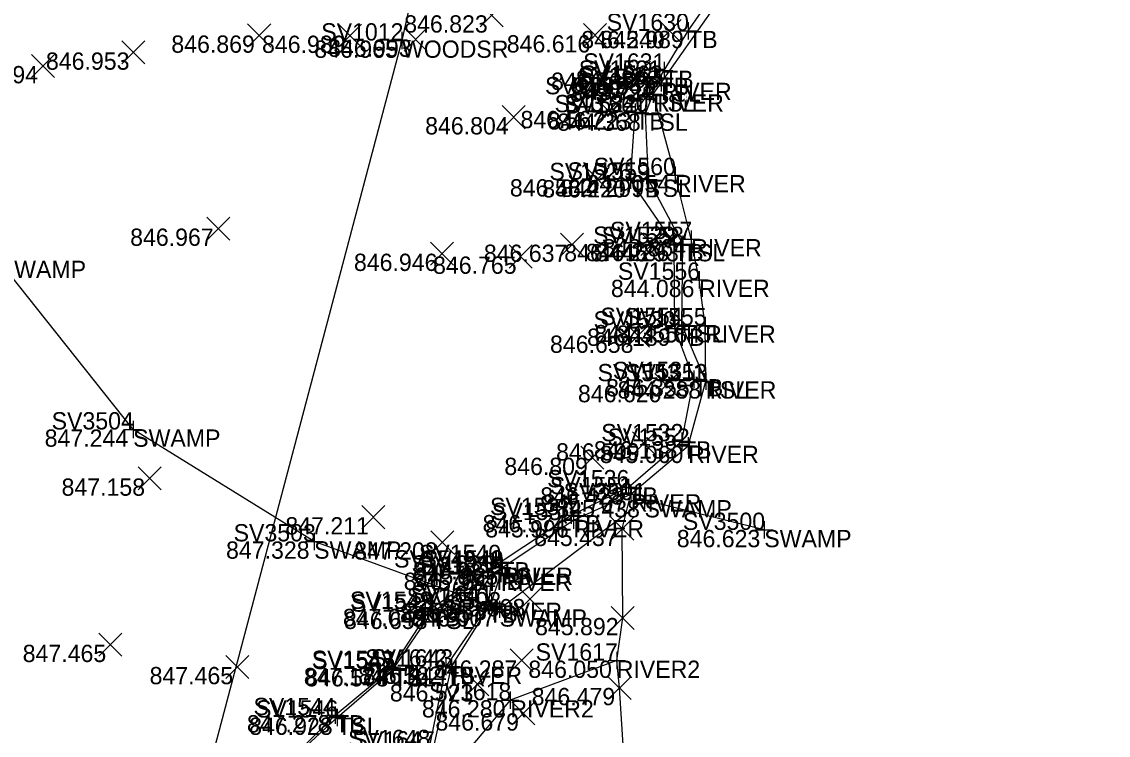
# Model space of a CAD drawing. Extents: x 2228183 to 2230895, y 679226 to 682223.
# Drawn here: x 2228345.6 to 2228408.5, y 680526.8 to 680568.1 of the extents above; entities that cross this region are included whole.
import ezdxf

# ---------------------------------------------------------------- set-up
doc = ezdxf.new("R2010")
doc.units = 0
for name, color, linetype in [('HY_X_Water_Edge', 7, 'Continuous'), ('SC_Scratch1', 7, 'Continuous'), ('SV_P_Control_Cells_Set', 7, 'Continuous'), ('SV_X_Random_Point', 7, 'Continuous'), ('SV_X_Shot_Marker', 7, 'Continuous'), ('SV_X_Terrain_Boundary', 7, 'Continuous'), ('SV_X_Text_Comment', 7, 'Continuous'), ('SV_X_Toe_of_Slope', 7, 'Continuous'), ('SV_X_Top_of_Bank', 7, 'Continuous'), ('VG_X_Tree_Line_Rt', 7, 'Continuous')]:
    doc.layers.add(name, color=color, linetype=linetype)

msp = doc.modelspace()

# ---------------------------------------------------------------- linework, layer by layer
at = {"layer": 'HY_X_Water_Edge'}
for points in [[(2228351.874, 680498.059), (2228352.446, 680499.738), (2228356.332, 680506.475), (2228359.575, 680512.281), (2228364.446, 680519.192), (2228367.217, 680520.658), (2228368.827, 680522.654), (2228367.913, 680524.402), (2228369.445, 680526.065), (2228370.483, 680530.802), (2228372.796, 680534.496), (2228373.339, 680536.179), (2228373.425, 680536.53), (2228377.537, 680539.273), (2228380.858, 680540.77), (2228384.182, 680543.574), (2228385.199, 680547.303), (2228385.16, 680550.533), (2228384.814, 680553.173), (2228384.351, 680555.526), (2228383.424, 680559.226), (2228382.159, 680563.898), (2228382.611, 680564.564)], [(2228388.587, 680538.705), (2228381.654, 680540.428), (2228373.267, 680534.114), (2228362.534, 680538.041), (2228352.058, 680544.515), (2228344.28, 680554.272), (2228336.684, 680545.185), (2228336.291, 680530.248), (2228335.4, 680519.473), (2228335.533, 680511.573), (2228332.556, 680502.567), (2228338.972, 680492.245), (2228338.927, 680481.209), (2228345.953, 680472.044), (2228352.301, 680471.046)], [(2228380.046, 680531.148), (2228373.886, 680528.859), (2228371.308, 680525.808), (2228369.351, 680519.348), (2228367.828, 680517.799), (2228365.066, 680517.912), (2228360.832, 680511.915), (2228358.717, 680505.916)]]:
    msp.add_lwpolyline(points, dxfattribs=at)
at = {"layer": 'SV_X_Random_Point'}
for p, q in [((2228372.144, 680567.799), (2228373.478, 680569.134)), ((2228372.144, 680569.134), (2228373.478, 680567.799)), ((2228358.685, 680566.633), (2228360.019, 680567.968)), ((2228358.685, 680567.968), (2228360.019, 680566.633)), ((2228363.933, 680566.623), (2228365.267, 680567.958)), ((2228363.933, 680567.958), (2228365.267, 680566.623)), ((2228367.739, 680566.399), (2228369.073, 680567.734)), ((2228367.739, 680567.734), (2228369.073, 680566.399)), ((2228378.119, 680566.649), (2228379.453, 680567.984)), ((2228378.119, 680567.984), (2228379.453, 680566.649)), ((2228382.441, 680566.89), (2228383.775, 680568.225)), ((2228382.441, 680568.225), (2228383.775, 680566.89)), ((2228351.407, 680565.652), (2228352.741, 680566.987)), ((2228351.407, 680566.987), (2228352.741, 680565.652)), ((2228346.173, 680564.867), (2228347.507, 680566.202)), ((2228346.173, 680566.202), (2228347.507, 680564.867)), ((2228380.664, 680564.486), (2228381.998, 680565.821)), ((2228380.664, 680565.821), (2228381.998, 680564.486)), ((2228373.412, 680561.91), (2228374.746, 680563.245)), ((2228373.412, 680563.245), (2228374.746, 680561.91)), ((2228378.905, 680562.27), (2228380.239, 680563.605)), ((2228378.905, 680563.605), (2228380.239, 680562.27)), ((2228378.268, 680558.322), (2228379.602, 680559.657)), ((2228378.268, 680559.657), (2228379.602, 680558.322)), ((2228356.312, 680555.466), (2228357.646, 680556.801)), ((2228356.312, 680556.801), (2228357.646, 680555.466)), ((2228376.785, 680554.537), (2228378.119, 680555.872)), ((2228376.785, 680555.872), (2228378.119, 680554.537)), ((2228381.443, 680554.569), (2228382.777, 680555.904)), ((2228381.443, 680555.904), (2228382.777, 680554.569)), ((2228369.273, 680554.014), (2228370.607, 680555.349)), ((2228369.273, 680555.349), (2228370.607, 680554.014)), ((2228373.819, 680553.85), (2228375.153, 680555.185)), ((2228373.819, 680555.185), (2228375.153, 680553.85)), ((2228380.617, 680549.279), (2228381.951, 680550.614)), ((2228380.617, 680550.614), (2228381.951, 680549.279)), ((2228382.249, 680546.42), (2228383.583, 680547.755)), ((2228382.249, 680547.755), (2228383.583, 680546.42)), ((2228380.954, 680543.049), (2228382.288, 680544.384)), ((2228380.954, 680544.384), (2228382.288, 680543.049)), ((2228377.96, 680542.215), (2228379.294, 680543.55)), ((2228377.96, 680543.55), (2228379.294, 680542.215)), ((2228352.345, 680541.016), (2228353.679, 680542.351)), ((2228352.345, 680542.351), (2228353.679, 680541.016)), ((2228365.284, 680538.776), (2228366.618, 680540.111)), ((2228365.284, 680540.111), (2228366.618, 680538.776)), ((2228379.696, 680538.107), (2228381.03, 680539.442)), ((2228379.696, 680539.442), (2228381.03, 680538.107)), ((2228369.283, 680537.322), (2228370.617, 680538.657)), ((2228369.283, 680538.657), (2228370.617, 680537.322)), ((2228374.355, 680534.043), (2228375.689, 680535.378)), ((2228374.355, 680535.378), (2228375.689, 680534.043)), ((2228379.726, 680532.948), (2228381.06, 680534.283)), ((2228379.726, 680534.283), (2228381.06, 680532.948)), ((2228350.067, 680531.398), (2228351.401, 680532.733)), ((2228350.067, 680532.733), (2228351.401, 680531.398)), ((2228373.883, 680530.494), (2228375.217, 680531.829)), ((2228373.883, 680531.829), (2228375.217, 680530.494)), ((2228357.412, 680530.114), (2228358.746, 680531.449)), ((2228357.412, 680531.449), (2228358.746, 680530.114)), ((2228371.313, 680529.118), (2228372.647, 680530.453)), ((2228371.313, 680530.453), (2228372.647, 680529.118)), ((2228379.541, 680528.902), (2228380.875, 680530.237)), ((2228379.541, 680530.237), (2228380.875, 680528.902)), ((2228373.971, 680527.434), (2228375.305, 680528.769)), ((2228373.971, 680528.769), (2228375.305, 680527.434))]:
    msp.add_line(p, q, dxfattribs=at)
at = {"layer": 'SV_X_Shot_Marker'}
for p, q in [((2228384.177, 680568.068), (2228384.177, 680567.068)), ((2228367.114, 680567.008), (2228368.114, 680567.008)), ((2228367.614, 680567.508), (2228367.614, 680566.508)), ((2228367.614, 680567.008), (2228367.614, 680567.008)), ((2228383.677, 680567.568), (2228384.677, 680567.568)), ((2228384.177, 680567.568), (2228384.177, 680567.568)), ((2228382.784, 680565.766), (2228382.784, 680564.766)), ((2228382.284, 680565.266), (2228383.284, 680565.266)), ((2228382.529, 680565.357), (2228382.529, 680564.357)), ((2228382.784, 680565.266), (2228382.784, 680565.266)), ((2228382.029, 680564.857), (2228383.029, 680564.857)), ((2228382.111, 680564.564), (2228383.111, 680564.564)), ((2228382.529, 680564.857), (2228382.529, 680564.857)), ((2228382.611, 680565.064), (2228382.611, 680564.064)), ((2228382.611, 680564.564), (2228382.611, 680564.564)), ((2228381.659, 680563.898), (2228382.659, 680563.898)), ((2228381.659, 680563.898), (2228382.659, 680563.898)), ((2228382.159, 680564.398), (2228382.159, 680563.398)), ((2228382.159, 680564.398), (2228382.159, 680563.398)), ((2228382.159, 680563.898), (2228382.159, 680563.898)), ((2228382.159, 680563.898), (2228382.159, 680563.898)), ((2228381.121, 680563.36), (2228381.121, 680562.36)), ((2228381.702, 680563.288), (2228381.702, 680562.288)), ((2228380.621, 680562.86), (2228381.621, 680562.86)), ((2228381.121, 680562.86), (2228381.121, 680562.86)), ((2228381.202, 680562.788), (2228382.202, 680562.788)), ((2228381.702, 680562.788), (2228381.702, 680562.788)), ((2228380.853, 680559.434), (2228380.853, 680558.434)), ((2228381.881, 680559.464), (2228381.881, 680558.464)), ((2228383.424, 680559.726), (2228383.424, 680558.726)), ((2228380.353, 680558.934), (2228381.353, 680558.934)), ((2228380.853, 680558.934), (2228380.853, 680558.934)), ((2228381.381, 680558.964), (2228382.381, 680558.964)), ((2228381.881, 680558.964), (2228381.881, 680558.964)), ((2228382.924, 680559.226), (2228383.924, 680559.226)), ((2228383.424, 680559.226), (2228383.424, 680559.226)), ((2228383.363, 680555.752), (2228383.363, 680554.752)), ((2228383.873, 680555.738), (2228383.873, 680554.738)), ((2228384.351, 680556.026), (2228384.351, 680555.026)), ((2228382.863, 680555.252), (2228383.863, 680555.252)), ((2228383.363, 680555.252), (2228383.363, 680555.252)), ((2228383.373, 680555.238), (2228384.373, 680555.238)), ((2228383.851, 680555.526), (2228384.851, 680555.526)), ((2228383.873, 680555.238), (2228383.873, 680555.238)), ((2228384.351, 680555.526), (2228384.351, 680555.526)), ((2228384.314, 680553.173), (2228385.314, 680553.173)), ((2228384.814, 680553.673), (2228384.814, 680552.673)), ((2228384.814, 680553.173), (2228384.814, 680553.173)), ((2228383.414, 680550.851), (2228383.414, 680549.851)), ((2228383.823, 680551.058), (2228383.823, 680550.058)), ((2228385.16, 680551.033), (2228385.16, 680550.033)), ((2228382.914, 680550.351), (2228383.914, 680550.351)), ((2228383.323, 680550.558), (2228384.323, 680550.558)), ((2228383.414, 680550.351), (2228383.414, 680550.351)), ((2228383.823, 680550.558), (2228383.823, 680550.558)), ((2228384.66, 680550.533), (2228385.66, 680550.533)), ((2228385.16, 680550.533), (2228385.16, 680550.533)), ((2228384.501, 680547.928), (2228384.501, 680546.928)), ((2228385.199, 680547.803), (2228385.199, 680546.803)), ((2228385.199, 680547.803), (2228385.199, 680546.803)), ((2228384.001, 680547.428), (2228385.001, 680547.428)), ((2228384.501, 680547.428), (2228384.501, 680547.428)), ((2228384.699, 680547.303), (2228385.699, 680547.303)), ((2228384.699, 680547.303), (2228385.699, 680547.303)), ((2228385.199, 680547.303), (2228385.199, 680547.303)), ((2228385.199, 680547.303), (2228385.199, 680547.303)), ((2228352.058, 680545.015), (2228352.058, 680544.015)), ((2228351.558, 680544.515), (2228352.558, 680544.515)), ((2228352.058, 680544.515), (2228352.058, 680544.515)), ((2228383.322, 680543.833), (2228384.322, 680543.833)), ((2228383.822, 680544.333), (2228383.822, 680543.333)), ((2228383.822, 680543.833), (2228383.822, 680543.833)), ((2228384.182, 680544.074), (2228384.182, 680543.074)), ((2228383.682, 680543.574), (2228384.682, 680543.574)), ((2228384.182, 680543.574), (2228384.182, 680543.574)), ((2228380.722, 680541.67), (2228380.722, 680540.67)), ((2228380.858, 680541.27), (2228380.858, 680540.27)), ((2228380.222, 680541.17), (2228381.222, 680541.17)), ((2228380.358, 680540.77), (2228381.358, 680540.77)), ((2228380.722, 680541.17), (2228380.722, 680541.17)), ((2228380.858, 680540.77), (2228380.858, 680540.77)), ((2228381.654, 680540.928), (2228381.654, 680539.928)), ((2228377.405, 680540.067), (2228377.405, 680539.067)), ((2228381.154, 680540.428), (2228382.154, 680540.428)), ((2228381.654, 680540.428), (2228381.654, 680540.428)), ((2228376.905, 680539.567), (2228377.905, 680539.567)), ((2228377.405, 680539.567), (2228377.405, 680539.567)), ((2228377.537, 680539.773), (2228377.537, 680538.773)), ((2228377.037, 680539.273), (2228378.037, 680539.273)), ((2228377.537, 680539.273), (2228377.537, 680539.273)), ((2228388.087, 680538.705), (2228389.087, 680538.705)), ((2228388.587, 680539.205), (2228388.587, 680538.205)), ((2228388.587, 680538.705), (2228388.587, 680538.705)), ((2228362.534, 680538.541), (2228362.534, 680537.541)), ((2228362.034, 680538.041), (2228363.034, 680538.041)), ((2228362.534, 680538.041), (2228362.534, 680538.041)), ((2228372.807, 680536.845), (2228373.807, 680536.845)), ((2228373.307, 680537.345), (2228373.307, 680536.345)), ((2228373.307, 680536.845), (2228373.307, 680536.845)), ((2228373.425, 680537.03), (2228373.425, 680536.03)), ((2228373.425, 680537.03), (2228373.425, 680536.03)), ((2228372.338, 680536.235), (2228373.338, 680536.235)), ((2228372.838, 680536.735), (2228372.838, 680535.735)), ((2228372.838, 680536.235), (2228372.838, 680536.235)), ((2228372.839, 680536.179), (2228373.839, 680536.179)), ((2228372.925, 680536.53), (2228373.925, 680536.53)), ((2228372.925, 680536.53), (2228373.925, 680536.53)), ((2228373.339, 680536.679), (2228373.339, 680535.679)), ((2228373.339, 680536.179), (2228373.339, 680536.179)), ((2228373.425, 680536.53), (2228373.425, 680536.53)), ((2228373.425, 680536.53), (2228373.425, 680536.53)), ((2228372.796, 680534.996), (2228372.796, 680533.996)), ((2228369.277, 680534.64), (2228369.277, 680533.64)), ((2228369.362, 680534.477), (2228369.362, 680533.477)), ((2228372.102, 680534.347), (2228373.102, 680534.347)), ((2228372.296, 680534.496), (2228373.296, 680534.496)), ((2228372.602, 680534.847), (2228372.602, 680533.847)), ((2228372.602, 680534.347), (2228372.602, 680534.347)), ((2228372.796, 680534.496), (2228372.796, 680534.496)), ((2228373.267, 680534.614), (2228373.267, 680533.614)), ((2228368.777, 680534.14), (2228369.777, 680534.14)), ((2228368.862, 680533.977), (2228369.862, 680533.977)), ((2228369.277, 680534.14), (2228369.277, 680534.14)), ((2228369.362, 680533.977), (2228369.362, 680533.977)), ((2228372.767, 680534.114), (2228373.767, 680534.114)), ((2228373.267, 680534.114), (2228373.267, 680534.114)), ((2228367.056, 680531.226), (2228367.056, 680530.226)), ((2228367.115, 680531.158), (2228367.115, 680530.158)), ((2228370.155, 680531.3), (2228370.155, 680530.3)), ((2228370.483, 680531.302), (2228370.483, 680530.302)), ((2228379.546, 680531.148), (2228380.546, 680531.148)), ((2228380.046, 680531.648), (2228380.046, 680530.648)), ((2228380.046, 680531.148), (2228380.046, 680531.148)), ((2228366.556, 680530.726), (2228367.556, 680530.726)), ((2228366.615, 680530.658), (2228367.615, 680530.658)), ((2228367.056, 680530.726), (2228367.056, 680530.726)), ((2228367.115, 680530.658), (2228367.115, 680530.658)), ((2228369.655, 680530.8), (2228370.655, 680530.8)), ((2228369.983, 680530.802), (2228370.983, 680530.802)), ((2228370.155, 680530.8), (2228370.155, 680530.8)), ((2228370.483, 680530.802), (2228370.483, 680530.802)), ((2228373.886, 680529.359), (2228373.886, 680528.359)), ((2228373.386, 680528.859), (2228374.386, 680528.859)), ((2228373.886, 680528.859), (2228373.886, 680528.859)), ((2228363.243, 680527.994), (2228364.243, 680527.994)), ((2228363.743, 680528.494), (2228363.743, 680527.494)), ((2228363.743, 680527.994), (2228363.743, 680527.994)), ((2228363.871, 680528.355), (2228363.871, 680527.355)), ((2228363.371, 680527.855), (2228364.371, 680527.855)), ((2228363.871, 680527.855), (2228363.871, 680527.855))]:
    msp.add_line(p, q, dxfattribs=at)
at = {"layer": 'SV_X_Terrain_Boundary'}
msp.add_lwpolyline([(2228380.627, 680522.966), (2228380.208, 680529.569), (2228380.046, 680531.148), (2228380.393, 680533.615), (2228380.363, 680538.774), (2228380.858, 680540.77), (2228384.182, 680543.574), (2228385.199, 680547.303), (2228385.16, 680550.533), (2228384.814, 680553.173), (2228384.351, 680555.526), (2228383.424, 680559.226), (2228382.159, 680563.898), (2228382.611, 680564.564), (2228386.807, 680570.527)], dxfattribs=at)
at = {"layer": 'SV_X_Toe_of_Slope'}
for points in [[(2228385.199, 680547.303), (2228383.823, 680550.558), (2228383.873, 680555.238), (2228381.881, 680558.964), (2228381.702, 680562.788), (2228382.159, 680563.898), (2228382.611, 680564.564), (2228386.807, 680570.527), (2228386.898, 680571.5), (2228386.756, 680573.081), (2228385.115, 680573.808)], [(2228360.066, 680524.342), (2228363.871, 680527.855), (2228367.115, 680530.658), (2228369.362, 680533.977), (2228373.425, 680536.53)]]:
    msp.add_lwpolyline(points, dxfattribs=at)
at = {"layer": 'SV_X_Top_of_Bank'}
for points in [[(2228360.066, 680524.342), (2228363.743, 680527.994), (2228367.056, 680530.726), (2228369.277, 680534.14), (2228373.307, 680536.845), (2228377.405, 680539.567), (2228380.722, 680541.17), (2228383.822, 680543.833), (2228384.501, 680547.428), (2228383.414, 680550.351), (2228383.363, 680555.252), (2228380.853, 680558.934), (2228381.121, 680562.86), (2228382.529, 680564.857), (2228382.784, 680565.266), (2228384.177, 680567.568), (2228386.266, 680570.571)], [(2228372.838, 680536.235), (2228372.602, 680534.347), (2228370.155, 680530.8), (2228369.195, 680526.145), (2228367.512, 680524.614), (2228368.575, 680522.729), (2228366.868, 680521.03), (2228364.322, 680519.479), (2228359.271, 680512.408), (2228356.116, 680506.48), (2228352.138, 680499.911), (2228351.874, 680498.059)]]:
    msp.add_lwpolyline(points, dxfattribs=at)
at = {"layer": 'VG_X_Tree_Line_Rt'}
msp.add_lwpolyline([(2228410.452, 680773.345), (2228402.142, 680728.483), (2228403.602, 680691.208), (2228374.606, 680596.133), (2228370.969, 680582.119), (2228367.614, 680567.008), (2228346.3, 680486.661), (2228340.655, 680455.186), (2228334.048, 680383.235)], dxfattribs=at)

# ---------------------------------------------------------------- texts
at = {"layer": 'SC_Scratch1'}
for s, p in [('846.823', (2228367.747, 680567.466)), ('846.869', (2228354.268, 680566.3)), ('846.989', (2228359.516, 680566.29)), ('846.965', (2228362.544, 680566.008)), ('846.993', (2228363.342, 680566.066)), ('846.616', (2228373.682, 680566.316)), ('846.240', (2228377.994, 680566.557)), ('845.989', (2228379.093, 680566.568)), ('846.953', (2228347.01, 680565.319)), ('846.894', (2228341.718, 680564.534)), ('846.369', (2228376.247, 680564.153)), ('845.898', (2228377.684, 680564.266)), ('843.724', (2228377.343, 680563.472)), ('845.948', (2228377.429, 680563.857)), ('843.712', (2228377.538, 680563.564)), ('843.840', (2228377.045, 680562.898)), ('843.840', (2228377.045, 680562.898)), ('846.804', (2228368.957, 680561.577)), ('846.567', (2228374.476, 680561.937)), ('846.223', (2228376.057, 680561.86)), ('844.368', (2228376.602, 680561.788)), ('846.582', (2228373.862, 680557.989)), ('846.220', (2228375.739, 680557.934)), ('844.299', (2228376.797, 680557.964)), ('844.054', (2228378.302, 680558.226)), ('846.967', (2228351.883, 680555.133)), ('846.637', (2228372.356, 680554.204)), ('846.446', (2228377.006, 680554.236)), ('846.286', (2228378.259, 680554.252)), ('844.293', (2228378.809, 680554.238)), ('843.864', (2228379.229, 680554.526)), ('846.946', (2228364.836, 680553.681)), ('846.765', (2228369.416, 680553.517)), ('844.086', (2228379.71, 680552.173)), ('846.189', (2228378.33, 680549.351)), ('844.355', (2228378.753, 680549.558)), ('844.184', (2228380.038, 680549.533)), ('846.658', (2228376.184, 680548.946)), ('846.620', (2228377.802, 680546.087)), ('846.355', (2228379.431, 680546.428)), ('844.288', (2228380.099, 680546.303)), ('844.288', (2228380.099, 680546.303)), ('847.244', (2228346.936, 680543.515)), ('846.599', (2228376.537, 680542.716)), ('846.138', (2228378.722, 680542.833)), ('845.060', (2228379.068, 680542.574)), ('846.809', (2228373.543, 680541.882)), ('847.158', (2228347.912, 680540.683)), ('846.428', (2228375.622, 680540.17)), ('845.707', (2228375.762, 680539.77)), ('845.438', (2228376.554, 680539.428)), ('847.211', (2228360.869, 680538.443)), ('846.574', (2228372.283, 680538.567)), ('845.996', (2228372.433, 680538.273)), ('845.437', (2228375.267, 680537.774)), ('846.623', (2228383.523, 680537.705)), ('847.328', (2228357.434, 680537.041)), ('847.208', (2228364.85, 680536.989)), ('846.983', (2228368.243, 680535.845)), ('846.764', (2228367.716, 680535.235)), ('845.964', (2228368.217, 680535.179)), ('845.965', (2228368.355, 680535.53)), ('845.965', (2228368.355, 680535.53)), ('846.557', (2228367.506, 680533.347)), ('845.958', (2228367.696, 680533.496)), ('845.808', (2228369.922, 680533.71)), ('847.049', (2228364.193, 680533.14)), ('846.658', (2228364.262, 680532.977)), ('846.007', (2228368.171, 680533.114)), ('845.892', (2228375.32, 680532.615)), ('847.465', (2228345.664, 680531.065)), ('846.287', (2228369.454, 680530.161)), ('846.050', (2228374.932, 680530.148)), ('847.465', (2228353.009, 680529.781)), ('847.124', (2228361.934, 680529.726)), ('846.578', (2228362.014, 680529.658)), ('846.562', (2228365.082, 680529.8)), ('846.444', (2228365.361, 680529.802)), ('846.523', (2228366.916, 680528.785)), ('846.479', (2228375.124, 680528.569)), ('846.280', (2228368.772, 680527.859)), ('847.278', (2228358.643, 680526.994)), ('846.679', (2228369.554, 680527.101)), ('846.928', (2228358.771, 680526.855))]:
    msp.add_text(s, height=1, dxfattribs=at).set_placement(p)
at = {"layer": 'SV_P_Control_Cells_Set'}
for s, p in [('SV1630', (2228379.465, 680567.568)), ('SV1012', (2228362.943, 680567.008)), ('SV1521', (2228377.849, 680564.857)), ('SV1631', (2228378.104, 680565.266)), ('SV1632', (2228377.794, 680564.472)), ('SV1563', (2228377.949, 680564.564)), ('SV1562_1', (2228375.896, 680563.898)), ('SV1562', (2228377.488, 680563.898)), ('SV1522', (2228376.45, 680562.86)), ('SV1561', (2228377.022, 680562.788)), ('SV1560', (2228378.712, 680559.226)), ('SV1526', (2228376.151, 680558.934)), ('SV1559', (2228377.199, 680558.964)), ('SV1557', (2228379.657, 680555.526)), ('SV1529', (2228378.681, 680555.252)), ('SV1558', (2228379.174, 680555.238)), ('SV1556', (2228380.112, 680553.173)), ('SV1530', (2228378.702, 680550.351)), ('SV1554', (2228379.103, 680550.558)), ('SV1555', (2228380.491, 680550.533)), ('SV1553_1', (2228378.936, 680547.303)), ('SV1531', (2228379.821, 680547.428)), ('SV1553', (2228380.537, 680547.303)), ('SV3504', (2228347.338, 680544.515)), ('SV1532', (2228379.151, 680543.833)), ('SV1552', (2228379.511, 680543.574)), ('SV1536', (2228376.02, 680541.17)), ('SV1551', (2228376.178, 680540.77)), ('SV3501', (2228376.974, 680540.428)), ('SV1537', (2228372.711, 680539.567)), ('SV1550', (2228372.825, 680539.273)), ('SV3500', (2228383.875, 680538.705)), ('SV3503', (2228357.872, 680538.041)), ('SV1549_1', (2228367.162, 680536.53)), ('SV1540', (2228368.595, 680536.845)), ('SV1549', (2228368.743, 680536.53)), ('SV1635', (2228368.169, 680536.235)), ('SV1636', (2228368.637, 680536.179)), ('SV1542', (2228364.606, 680534.14)), ('SV1548', (2228364.664, 680533.977)), ('SV1640', (2228367.89, 680534.347)), ('SV1641', (2228368.116, 680534.496)), ('SV3502', (2228368.596, 680534.114)), ('SV1642', (2228365.484, 680530.8)), ('SV1643', (2228365.821, 680530.802)), ('SV1617', (2228375.352, 680531.148)), ('SV1543', (2228362.394, 680530.726)), ('SV1547', (2228362.421, 680530.658)), ('SV1618', (2228369.187, 680528.859)), ('SV1544', (2228359.023, 680527.994)), ('SV1546', (2228359.169, 680527.855)), ('SV1648', (2228364.496, 680526.145)), ('SV1647', (2228364.751, 680526.065))]:
    msp.add_text(s, height=1, dxfattribs=at).set_placement(p)
at = {"layer": 'SV_X_Text_Comment'}
for s, p in [('WOODSR', (2228367.614, 680566.008)), ('TB', (2228384.177, 680566.568)), ('TB', (2228382.784, 680564.266)), ('TSL', (2228382.465, 680563.472)), ('TB', (2228382.529, 680563.857)), ('RIVER', (2228382.611, 680563.564)), ('TSL', (2228382.159, 680562.898)), ('RIVER', (2228382.159, 680562.898)), ('TB', (2228381.121, 680561.86)), ('TSL', (2228381.702, 680561.788)), ('TB', (2228380.853, 680557.934)), ('TSL', (2228381.881, 680557.964)), ('RIVER', (2228383.424, 680558.226)), ('TB', (2228383.363, 680554.252)), ('TSL', (2228383.873, 680554.238)), ('RIVER', (2228384.351, 680554.526)), ('SWAMP', (2228344.28, 680553.272)), ('RIVER', (2228384.814, 680552.173)), ('TB', (2228383.414, 680549.351)), ('TSL', (2228383.823, 680549.558)), ('RIVER', (2228385.16, 680549.533)), ('TB', (2228384.501, 680546.428)), ('TSL', (2228385.199, 680546.303)), ('RIVER', (2228385.199, 680546.303)), ('SWAMP', (2228352.058, 680543.515)), ('TB', (2228383.822, 680542.833)), ('RIVER', (2228384.182, 680542.574)), ('TB', (2228380.722, 680540.17)), ('RIVER', (2228380.858, 680539.77)), ('SWAMP', (2228381.654, 680539.428)), ('TB', (2228377.405, 680538.567)), ('RIVER', (2228377.537, 680538.273)), ('SWAMP', (2228388.587, 680537.705)), ('SWAMP', (2228362.534, 680537.041)), ('TB', (2228373.307, 680535.845)), ('TB', (2228372.838, 680535.235)), ('RIVER', (2228373.339, 680535.179)), ('TSL', (2228373.425, 680535.53)), ('RIVER', (2228373.425, 680535.53)), ('TB', (2228372.602, 680533.347)), ('RIVER', (2228372.796, 680533.496)), ('TB', (2228369.277, 680533.14)), ('TSL', (2228369.362, 680532.977)), ('SWAMP', (2228373.267, 680533.114)), ('RIVER2', (2228380.046, 680530.148)), ('TB', (2228367.056, 680529.726)), ('TSL', (2228367.115, 680529.658)), ('TB', (2228370.155, 680529.8)), ('RIVER', (2228370.483, 680529.802)), ('RIVER2', (2228373.886, 680527.859)), ('TB', (2228363.743, 680526.994)), ('TSL', (2228363.871, 680526.855))]:
    msp.add_text(s, height=1, dxfattribs=at).set_placement(p)

doc.saveas('drawing.dxf')
